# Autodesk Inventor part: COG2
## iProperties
Created: 2010-11
Part Number: COG2
Document SubType Name: Modeling
Designer: ROBERT
Density: 1 g/cm^3
Author: ROBERT
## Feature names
1. Extrusion2
2. Extrusion3
3. Fillet1
4. Fillet2
5. TaggingFeature1
